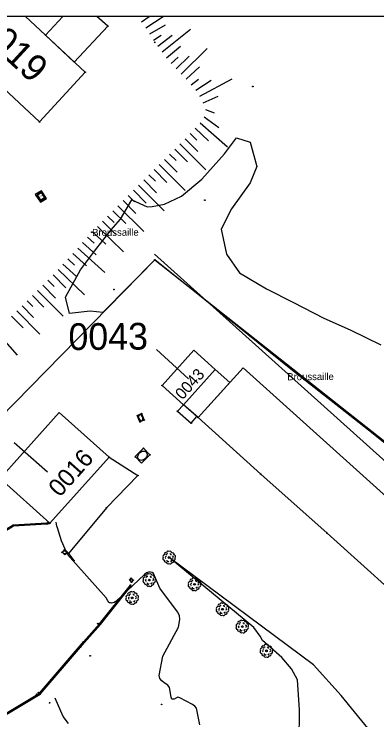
# Model space of a CAD drawing. Extents: x 344013 to 344423, y 298505 to 298795.
# Drawn here: x 344275.5 to 344325.2, y 298695.5 to 298792.2 of the extents above; entities that cross this region are included whole.
import ezdxf

# ---------------------------------------------------------------- set-up
doc = ezdxf.new("R2010")
doc.units = 0
for name, color, linetype in [('Default', 7, 'Continuous'), ('DH_CADRE -CARTOUCHE', 7, 'Continuous'), ('PC_CONCRETE', 7, 'Continuous'), ('PS_BOLT', 7, 'Continuous'), ('PS_CONST', 7, 'Continuous'), ('PS_HIDDEN', 7, 'Continuous'), ('PS_WELD', 7, 'Continuous'), ('RES_ELECTRICITE', 7, 'Continuous'), ('TOPO_COURBE NIVEAU', 7, 'Continuous'), ('TOPO_POINT', 7, 'Continuous'), ('TOPO_TALUS-TERRAIN NATUREL', 7, 'Continuous'), ('VOIRIE_BORDURE', 7, 'Continuous'), ('VOIRIE_ESPACE VERT', 7, 'Continuous')]:
    doc.layers.add(name, color=color, linetype=linetype)

# ---------------------------------------------------------------- blocks, each defined once
blk = doc.blocks.new('REG_INC')
at = {"layer": 'Default'}
for p, q in [((0, 1), (1, 1)), ((0, 0), (0, 1)), ((1, 1), (1, 0)), ((1, 0), (0, 0))]:
    blk.add_line(p, q, dxfattribs=at)
for centre, start, end in [((0.498, 0.5), 135.00554, 180.00554), ((0.5, 0.498), 90.00577, 135.00577), ((0.5, 0.5), 45.00687, 90.00687), ((0.499, 0.499), 0.00663, 45.00663), ((0.501, 0.5), 180.00663, 225.00663), ((0.499, 0.498), 225.00686, 270.00686), ((0.499, 0.5), 270.00577, 315.00577), ((0.501, 0.499), 315.00554, 0.00554)]:
    blk.add_arc(centre, 0.44, start, end, dxfattribs=at)
blk = doc.blocks.new('POINT_DISPLAY')
at = {"layer": 'Default'}
blk.add_circle((0, 0), 0.05, dxfattribs=at)
blk = doc.blocks.new('RES_ELECTRICITE')
at = {"layer": 'RES_ELECTRICITE'}
for points in [[(0, 0), (0, 1), (1, 1), (1, 0)], [(0.05, 0.05), (0.05, 0.95), (0.95, 0.95), (0.95, 0.05)]]:
    blk.add_lwpolyline(points, close=True, dxfattribs=at)
blk.add_text('EEC', height=0.2, dxfattribs=at).set_placement((0.237, 0.46))
blk = doc.blocks.new('ARB1')
at = {"layer": 'Default'}
blk.add_circle((0, 0), 0.122, dxfattribs=at)
for centre, radius, start, end in [((-0.613, 0.139), 0.241, 88.45835, 215.19284), ((-0.471, 0.503), 0.183, 53.95544, 222.20655), ((-0.373, -0.024), 0.149, 103.70924, 242.34652), ((-0.276, 0.37), 0.134, 52.43963, 209.54959), ((-0.153, 0.664), 0.211, 43.69255, 183.5969), ((0.139, 0.613), 0.241, 358.45835, 125.19284), ((0.164, 0.38), 0.112, 330.58954, 133.71274), ((0.501, 0.468), 0.183, 325.14445, 131.01755), ((0.458, 0.052), 0.137, 276.62143, 88.96702), ((0.613, -0.139), 0.241, 268.45835, 35.19284), ((0.664, 0.153), 0.211, 313.69255, 93.5969), ((-0.664, -0.153), 0.211, 133.69255, 273.5969), ((-0.478, -0.443), 0.19, 155.22426, 300.93774), ((-0.139, -0.613), 0.241, 178.45835, 305.19284), ((-0.163, -0.42), 0.148, 159.53711, 338.16632), ((0.153, -0.664), 0.211, 223.69255, 3.5969), ((0.271, -0.38), 0.112, 210.58954, 13.71274), ((0.448, -0.483), 0.188, 243.13234, 33.02965)]:
    blk.add_arc(centre, radius, start, end, dxfattribs=at)

msp = doc.modelspace()

# ---------------------------------------------------------------- linework, layer by layer
at = {"layer": 'DH_CADRE -CARTOUCHE'}
for points in [[(344012.906, 298504.876), (344422.906, 298504.876), (344422.906, 298791.876), (344012.906, 298791.876)], [(344282.183, 298791.876), (344279.804, 298789.297), (344283.741, 298785.631), (344288.331, 298790.56), (344286.829, 298791.876)], [(344300.695, 298736.911), (344309.284, 298729.159), (344318.375, 298721.074), (344331.766, 298709.041), (344345.307, 298697.002), (344354.351, 298688.866), (344356.37, 298691.11), (344358.623, 298689.083), (344360.288, 298690.966), (344358.051, 298692.978), (344360.392, 298695.581), (344306.859, 298743.741)], [(344273.541, 298728.568), (344280.403, 298722.45), (344288.5, 298731.494), (344281.65, 298737.626)]]:
    msp.add_lwpolyline(points, close=True, dxfattribs=at)
msp.add_lwpolyline([(344265.664, 298789.832), (344278.988, 298777.418), (344285.22, 298784.254), (344277.035, 298791.876)], dxfattribs=at)
at = {"layer": 'PS_BOLT'}
for points in [[(344279.092, 298766.421), (344279.938, 298766.936), (344279.224, 298767.998), (344278.377, 298767.483)], [(344298.719, 298738.678), (344297.89, 298737.796), (344299.759, 298736.16), (344300.548, 298737.042)]]:
    msp.add_lwpolyline(points, close=True, dxfattribs=at)
msp.add_lwpolyline([(344280.403, 298722.45), (344288.5, 298731.494), (344292.438, 298728.979), (344288.152, 298724.568), (344282.951, 298718.291), (344283.667, 298717.323), (344283.632, 298717.255)], dxfattribs=at)
at = {"layer": 'PS_CONST'}
for p, q in [((344294.982, 298746.239), (344299.386, 298742.214)), ((344275.5, 298733.485), (344280.074, 298729.46))]:
    msp.add_line(p, q, dxfattribs=at)
at = {"layer": 'PS_HIDDEN'}
for points in [[(344298.719, 298738.678), (344295.789, 298741.3), (344300.123, 298746.144), (344303.053, 298743.523)], [(344303.053, 298743.523), (344305.042, 298741.727), (344300.695, 298736.911), (344298.719, 298738.678)]]:
    msp.add_lwpolyline(points, close=True, dxfattribs=at)
at = {"layer": 'PS_WELD'}
msp.add_lwpolyline([(344267.039, 298730.273), (344294.784, 298758.546), (344373.471, 298696.387)], dxfattribs=at)
at = {"layer": 'TOPO_COURBE NIVEAU'}
for points in [[(344369.546, 298692.262), (344367.098, 298697.415), (344362.432, 298701.465), (344359.917, 298703.421), (344354.93, 298707.779), (344352.46, 298709.058), (344349.707, 298709.77), (344349.226, 298709.748), (344348.55, 298709.812), (344348.063, 298710.017), (344347.551, 298710.387), (344342.046, 298715.864), (344340.783, 298717.982), (344294.711, 298759.292)], [(344300.921, 298694.797), (344300.5, 298697.079), (344300.264, 298697.378), (344299.957, 298697.607), (344298.196, 298698.538), (344297.928, 298698.586), (344297.748, 298698.5), (344297.409, 298698.335), (344297.103, 298698.328), (344297.024, 298698.596), (344296.775, 298699.919), (344296.539, 298700.249), (344296.044, 298700.588), (344295.714, 298700.856), (344295.463, 298701.156), (344295.378, 298701.557), (344295.893, 298704.223), (344298, 298708.207), (344298.214, 298709.268), (344298.152, 298709.804), (344297.869, 298710.293), (344295.474, 298713.547), (344294.596, 298715.547), (344294.416, 298715.697), (344294.188, 298715.751), (344293.897, 298715.729), (344293.613, 298715.635), (344293.362, 298715.415), (344289.428, 298711.73), (344289.192, 298711.589), (344288.853, 298711.503), (344288.72, 298711.527), (344288.571, 298711.535), (344288.476, 298711.63), (344288.351, 298711.803), (344288.107, 298712.205), (344282.824, 298718.166), (344281.986, 298720.033), (344281.422, 298721.811), (344281.352, 298722.039), (344281.305, 298722.291), (344281.274, 298722.591)], [(344314.248, 298691.949), (344314.62, 298694.85), (344314.584, 298696.883), (344314.324, 298700.991), (344313.484, 298702.496), (344312.173, 298704.048), (344309.551, 298706.395), (344309.191, 298706.947), (344308.365, 298708.152), (344296.729, 298717.745)], [(344320.328, 298698.849), (344316.5, 298703.026), (344296.729, 298717.745)], [(344282.944, 298694.98), (344282.229, 298695.98), (344281.1, 298698.452)], [(344324.981, 298693.114), (344320.328, 298698.849)]]:
    msp.add_lwpolyline(points, dxfattribs=at)
at = {"layer": 'TOPO_TALUS-TERRAIN NATUREL'}
for p, q in [((344292.964, 298791.134), (344293.975, 298791.876)), ((344293.556, 298790.327), (344295.913, 298791.876)), ((344294.082, 298789.478), (344296.241, 298790.741)), ((344295.775, 298787.008), (344299.68, 298790.133)), ((344294.587, 298788.615), (344295.624, 298789.314)), ((344295.164, 298787.799), (344297.143, 298789.328)), ((344296.387, 298786.217), (344298.312, 298787.812)), ((344298.379, 298783.976), (344301.939, 298787.489)), ((344297.025, 298785.446), (344297.952, 298786.285)), ((344297.676, 298784.688), (344299.457, 298786.444)), ((344299.082, 298783.264), (344300.899, 298784.982)), ((344299.755, 298782.524), (344300.745, 298783.287)), ((344300.961, 298780.936), (344305.365, 298783.307)), ((344300.415, 298781.775), (344302.511, 298783.14)), ((344301.408, 298780.045), (344303.472, 298780.942)), ((344301.713, 298779.114), (344302.889, 298778.69)), ((344301.527, 298778.144), (344303.53, 298776.647)), ((344300.323, 298776.553), (344302.15, 298774.845)), ((344300.98, 298777.307), (344304.753, 298774.025)), ((344299.632, 298775.83), (344300.515, 298774.945)), ((344298.924, 298775.124), (344300.689, 298773.353)), ((344297.507, 298773.712), (344299.272, 298771.941)), ((344298.215, 298774.418), (344301.745, 298770.876)), ((344296.798, 298773.006), (344297.681, 298772.12)), ((344296.089, 298772.3), (344297.855, 298770.529)), ((344294.673, 298770.888), (344296.438, 298769.117)), ((344295.381, 298771.594), (344298.912, 298768.052)), ((344293.964, 298770.182), (344294.847, 298769.296)), ((344292.547, 298768.769), (344296.074, 298765.223)), ((344293.256, 298769.475), (344295.021, 298767.705)), ((344291.838, 298768.064), (344293.599, 298766.288)), ((344291.128, 298767.36), (344292.008, 298766.472)), ((344289.707, 298765.951), (344293.26, 298762.431)), ((344290.417, 298766.655), (344292.178, 298764.88)), ((344289, 298765.243), (344290.793, 298763.499)), ((344288.303, 298764.526), (344289.199, 298763.655)), ((344286.908, 298763.093), (344290.492, 298759.605)), ((344287.605, 298763.81), (344289.397, 298762.066)), ((344286.21, 298762.376), (344288.039, 298760.671)), ((344285.541, 298761.632), (344286.474, 298760.799)), ((344284.209, 298760.14), (344287.939, 298756.809)), ((344284.875, 298760.886), (344286.74, 298759.22)), ((344283.543, 298759.394), (344285.394, 298757.713)), ((344282.865, 298758.657), (344283.784, 298757.81)), ((344281.509, 298757.187), (344285.113, 298753.719)), ((344282.187, 298757.922), (344284.025, 298756.227)), ((344280.825, 298756.457), (344282.591, 298754.686)), ((344280.117, 298755.751), (344281, 298754.865)), ((344278.7, 298754.339), (344282.226, 298750.792)), ((344279.408, 298755.045), (344281.174, 298753.273)), ((344277.991, 298753.633), (344279.576, 298752.035)), ((344277.281, 298752.929), (344278.073, 298752.13)), ((344275.86, 298751.52), (344279.031, 298748.324)), ((344276.571, 298752.224), (344278.156, 298750.626)), ((344275.15, 298750.815), (344276.735, 298749.218)), ((344272.923, 298748.805), (344275.921, 298745.448))]:
    msp.add_line(p, q, dxfattribs=at)
at = {"layer": 'VOIRIE_BORDURE'}
for points in [[(344257.644, 298703.788), (344266.054, 298713.165), (344272.82, 298720.69), (344275.38, 298722.243), (344279.959, 298722.487), (344280.269, 298722.569)], [(344257.755, 298703.688), (344266.166, 298713.064), (344272.917, 298720.574), (344275.425, 298722.095), (344279.982, 298722.338), (344280.403, 298722.45)], [(344270.166, 298693.919), (344278.95, 298699.134), (344284.997, 298706.184), (344287.211, 298708.679), (344291.43, 298713.968)], [(344270.243, 298693.79), (344279.037, 298699.029), (344284.564, 298705.439), (344285.119, 298706.096), (344287.326, 298708.582), (344291.547, 298713.875)], [(344291.547, 298713.875), (344291.43, 298713.968)]]:
    msp.add_lwpolyline(points, dxfattribs=at)
at = {"layer": 'VOIRIE_ESPACE VERT'}
for points in [[(344339.365, 298722.962), (344324.681, 298734.684), (344313.436, 298743.57), (344301.632, 298753.048), (344294.784, 298758.546), (344287.642, 298751.299), (344285.912, 298751.476), (344283.08, 298751.198), (344282.525, 298753.393), (344284.59, 298757.181), (344286.505, 298759.732), (344288.784, 298762.649), (344290.085, 298764.086), (344291.63, 298766.773), (344293.706, 298765.81), (344294.428, 298765.828), (344296.08, 298766.171), (344298.443, 298767.269), (344301.193, 298769.57), (344304.305, 298773.049), (344305.986, 298775.259)], [(344305.986, 298775.259), (344307.829, 298774.651), (344308.767, 298771.329), (344307.85, 298769.065), (344305.296, 298765.529), (344303.86, 298762.731), (344304.602, 298759.324), (344306.36, 298756.741), (344310.099, 298754.549), (344313.763, 298752.686), (344317.922, 298750.531), (344321.545, 298748.944), (344325.748, 298746.901)]]:
    msp.add_lwpolyline(points, dxfattribs=at)

# ---------------------------------------------------------------- block references
at = {"layer": 'PC_CONCRETE'}
for p, xscale, yscale, rotation in [((344292.739, 298736.316), 0.643122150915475, 0.9589037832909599, 24.122249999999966), ((344293.214, 298732.704), 1.2468560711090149, -1.619293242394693, -45.29745000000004), ((344282.402, 298718.809), 0.5031129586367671, -0.49179402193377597, -44.43849000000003), ((344291.586, 298714.373), 0.365810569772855, 0.384590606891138, 50.00337)]:
    msp.add_blockref('REG_INC', p, dxfattribs=dict(at, xscale=xscale, yscale=yscale, rotation=rotation))
at = {"layer": 'RES_ELECTRICITE', "xscale": 0.6900656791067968, "yscale": 0.978195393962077, "rotation": 31.32458999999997}
msp.add_blockref('RES_ELECTRICITE', (344279.137, 298766.624), dxfattribs=at)
at = {"layer": 'TOPO_POINT'}
for p in [(344288.331, 298790.56), (344279.804, 298789.297), (344294.755, 298788.328), (344285.22, 298784.254), (344308.196, 298782.29), (344278.988, 298777.418), (344279.179, 298767.795), (344279.726, 298766.983), (344279.137, 298766.624), (344301.616, 298766.699), (344286.152, 298762.316), (344294.784, 298758.546), (344289.172, 298754.469), (344295.789, 298741.3), (344297.89, 298737.796), (344298.703, 298738.645), (344298.719, 298738.678), (344292.947, 298737.459), (344300.548, 298737.042), (344300.695, 298736.911), (344292.739, 298736.316), (344293.326, 298736.578), (344299.759, 298736.16), (344293.214, 298732.704), (344288.5, 298731.494), (344292.113, 298731.514), (344294.091, 298731.818), (344309.284, 298729.159), (344292.438, 298728.979), (344288.152, 298724.568), (344279.982, 298722.338), (344280.126, 298722.375), (344280.348, 298722.428), (344280.403, 298722.45), (344318.375, 298721.074), (344282.059, 298718.457), (344282.402, 298718.809), (344282.761, 298718.457), (344282.951, 298718.291), (344296.729, 298717.745), (344283.667, 298717.323), (344291.524, 298714.898), (344291.821, 298714.654), (344294.017, 298714.655), (344291.43, 298713.968), (344291.586, 298714.373), (344300.203, 298714.071), (344291.667, 298712.203), (344304.048, 298710.653), (344286.972, 298708.677), (344287.211, 298708.679), (344306.762, 298708.275), (344284.997, 298706.184), (344284.564, 298705.439), (344310.069, 298704.961), (344285.916, 298704.284), (344278.828, 298699.223), (344278.95, 298699.134), (344278.613, 298699.012), (344279.037, 298699.029), (344280.354, 298697.823), (344295.701, 298697.622)]:
    msp.add_blockref('POINT_DISPLAY', p, dxfattribs=at)
at = {"layer": 'VOIRIE_ESPACE VERT'}
for p in [(344296.729, 298717.745), (344294.017, 298714.655), (344300.203, 298714.071), (344291.667, 298712.203), (344304.048, 298710.653), (344306.762, 298708.275), (344310.069, 298704.961)]:
    msp.add_blockref('ARB1', p, dxfattribs=at)

# ---------------------------------------------------------------- texts
at = {"layer": 'PS_CONST'}
for s, height, rotation, p in [('0019', 3.662, 317.32702, (344269.976, 298789.978)), ('Broussaille', 0.97578, 0.36646, (344286.184, 298761.796)), ('0043', 3.662, 0.36647, (344282.948, 298746.168)), ('0043', 1.5764, 48.15386, (344298.575, 298739.267)), ('Broussaille', 0.97578, 0.36646, (344312.925, 298742.025)), ('0016', 2.4027, 48.15386, (344281.749, 298725.903))]:
    msp.add_text(s, height=height, rotation=rotation, dxfattribs=at).set_placement(p)

doc.saveas('drawing.dxf')
